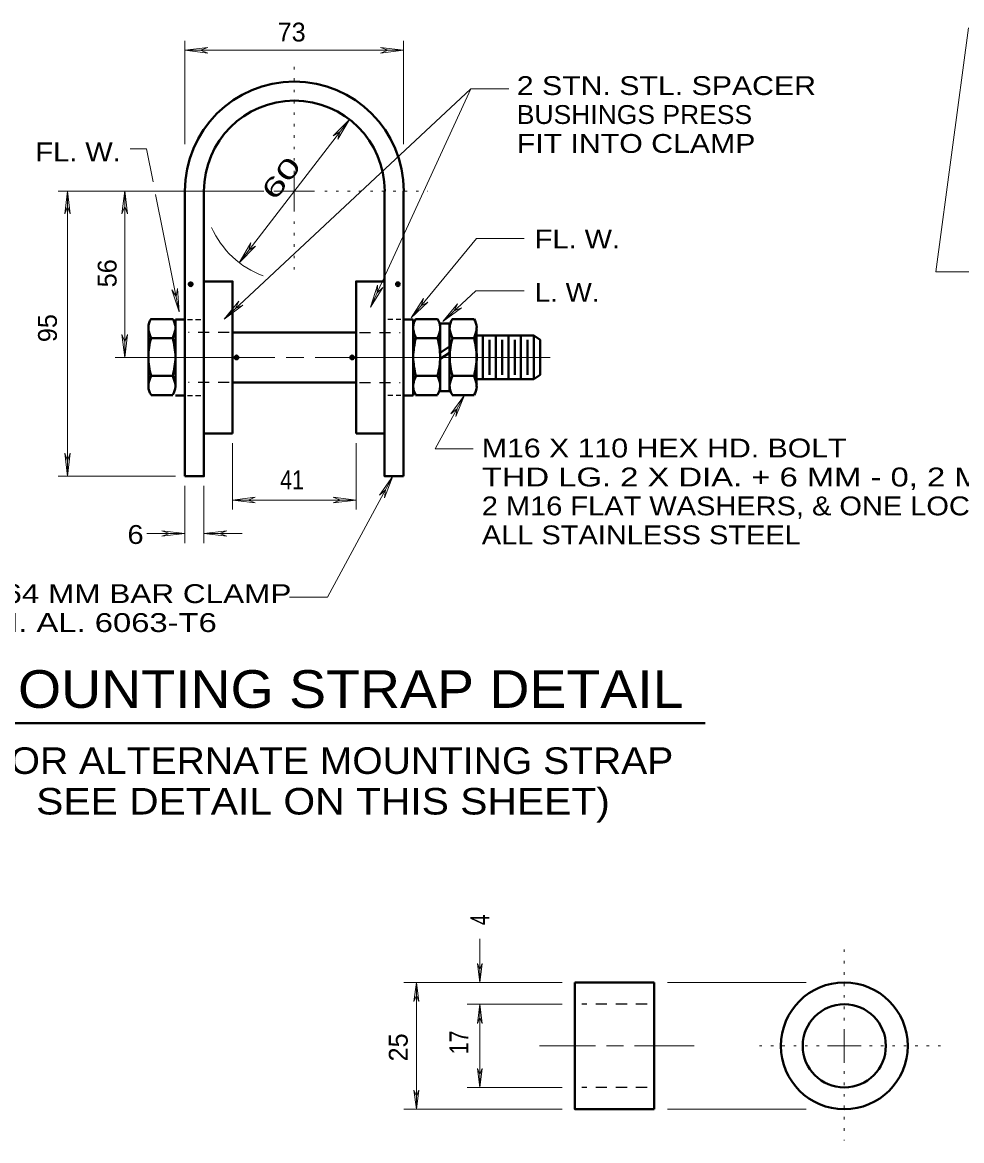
# Model space of a CAD drawing. Extents: x 312583 to 312854, y 144419 to 144597.
# Drawn here: x 312688.47 to 312726.34, y 144489.99 to 144535.08 of the extents above; entities that cross this region are included whole.
import ezdxf
from ezdxf.enums import TextEntityAlignment as Align

# ---------------------------------------------------------------- set-up
doc = ezdxf.new("R2010")
doc.units = 0
doc.header["$LTSCALE"] = 0.3
doc.header["$PDMODE"] = 32
doc.header["$PDSIZE"] = 0.15
doc.linetypes.add('DOTTED', pattern=[1.5, 0.3, -1.2])
doc.linetypes.add('SHORT_DASHED', pattern=[2.7, 1.5, -1.2])
doc.layers.add('1', color=7, linetype='Continuous', lineweight=40)

msp = doc.modelspace()

# ---------------------------------------------------------------- linework, layer by layer
at = {"layer": '1', "lineweight": 13}
for p, q in [((312695.0286, 144530.1636), (312695.0286, 144534.3343)), ((312703.8453, 144530.1636), (312703.8453, 144534.3343)), ((312695.0286, 144533.951), (312695.9486, 144534.066)), ((312695.0286, 144533.951), (312703.8453, 144533.951)), ((312695.0286, 144533.951), (312695.9486, 144533.836)), ((312695.9486, 144534.066), (312695.6573, 144533.951)), ((312695.9486, 144533.836), (312695.6573, 144533.951)), ((312702.9176, 144534.066), (312703.2166, 144533.951)), ((312703.8453, 144533.951), (312702.9176, 144534.066)), ((312702.9176, 144533.836), (312703.2166, 144533.951)), ((312703.8453, 144533.951), (312702.9176, 144533.836)), ((312696.608, 144523.118), (312706.5516, 144532.4023)), ((312702.5113, 144523.5933), (312706.5516, 144532.4023)), ((312706.5516, 144532.4023), (312708.085, 144532.4023)), ((312697.2136, 144525.3873), (312701.6603, 144531.168)), ((312701.6603, 144531.168), (312701.001, 144530.5086)), ((312701.6603, 144531.168), (312701.185, 144530.363)), ((312701.001, 144530.5086), (312701.277, 144530.6696)), ((312701.185, 144530.363), (312701.277, 144530.6696)), ((312692.8192, 144529.9828), (312693.4713, 144529.9828)), ((312693.4713, 144529.9828), (312693.7406, 144528.6456)), ((312699.437, 144528.2776), (312699.437, 144529.098)), ((312698.2103, 144528.2776), (312689.915, 144528.2776)), ((312690.2983, 144528.2776), (312690.1833, 144527.3576)), ((312690.2983, 144528.2776), (312690.2983, 144516.7776)), ((312690.2983, 144528.2776), (312690.4056, 144527.3576)), ((312692.5983, 144528.2853), (312692.4833, 144527.3576)), ((312692.5983, 144521.5693), (312692.5983, 144528.2853)), ((312692.5983, 144528.2853), (312692.7056, 144527.3576)), ((312693.8403, 144528.132), (312694.791, 144523.4093)), ((312699.437, 144528.2776), (312698.6166, 144528.2776)), ((312699.437, 144528.2776), (312699.437, 144527.4573)), ((312699.437, 144528.2776), (312700.2573, 144528.2776)), ((312690.1833, 144527.3576), (312690.2983, 144527.649)), ((312690.4056, 144527.3576), (312690.2983, 144527.649)), ((312692.4833, 144527.3576), (312692.5983, 144527.6566)), ((312692.7056, 144527.3576), (312692.5983, 144527.6566)), ((312697.2136, 144525.3873), (312697.689, 144526.1923)), ((312697.689, 144526.1923), (312697.597, 144525.8933)), ((312706.7893, 144526.361), (312704.152, 144523.164)), ((312706.7893, 144526.361), (312708.706, 144526.361)), ((312697.2136, 144525.3873), (312697.873, 144526.0543)), ((312697.873, 144526.0543), (312697.597, 144525.8933)), ((312694.4996, 144524.2986), (312694.6683, 144524.0303)), ((312694.791, 144523.4093), (312694.4996, 144524.2986)), ((312694.722, 144524.3446), (312694.6683, 144524.0303)), ((312694.791, 144523.4093), (312694.722, 144524.3446)), ((312702.5113, 144523.5933), (312702.795, 144524.4826)), ((312702.5113, 144523.5933), (312703.002, 144524.383)), ((312702.795, 144524.4826), (312702.7796, 144524.1683)), ((312703.002, 144524.383), (312702.7796, 144524.1683)), ((312696.608, 144523.118), (312697.206, 144523.8386)), ((312697.206, 144523.8386), (312697.068, 144523.5473)), ((312704.152, 144523.164), (312704.6503, 144523.946)), ((312704.6503, 144523.946), (312704.5506, 144523.647)), ((312706.7586, 144524.2526), (312705.4246, 144523.0183)), ((312706.7586, 144524.2526), (312708.6983, 144524.2526)), ((312696.608, 144523.118), (312697.3593, 144523.67)), ((312697.3593, 144523.67), (312697.068, 144523.5473)), ((312704.152, 144523.164), (312704.8266, 144523.8003)), ((312704.8266, 144523.8003), (312704.5506, 144523.647)), ((312705.4246, 144523.0183), (312706.0226, 144523.7313)), ((312705.4246, 144523.0183), (312706.1836, 144523.5626)), ((312706.0226, 144523.7313), (312705.8846, 144523.4476)), ((312706.1836, 144523.5626), (312705.8846, 144523.4476)), ((312692.4833, 144522.497), (312692.5983, 144522.198)), ((312692.5983, 144521.5693), (312692.4833, 144522.497)), ((312692.7056, 144522.497), (312692.5983, 144522.198)), ((312692.5983, 144521.5693), (312692.7056, 144522.497)), ((312698.655, 144521.5693), (312692.215, 144521.5693)), ((312699.8203, 144521.5693), (312699.115, 144521.5693)), ((312700.2803, 144521.5693), (312709.7563, 144521.5693)), ((312706.2986, 144520.0513), (312705.118, 144517.8893)), ((312706.2986, 144520.0513), (312705.7543, 144519.2923)), ((312706.2986, 144520.0513), (312705.9536, 144519.185)), ((312705.7543, 144519.2923), (312705.9996, 144519.4993)), ((312705.9536, 144519.185), (312705.9996, 144519.4993)), ((312696.9453, 144515.436), (312696.9453, 144518.1193)), ((312701.9286, 144515.436), (312701.9286, 144518.1193)), ((312690.1833, 144517.7053), (312690.2983, 144517.4063)), ((312690.2983, 144516.7776), (312690.1833, 144517.7053)), ((312690.4056, 144517.7053), (312690.2983, 144517.4063)), ((312690.2983, 144516.7776), (312690.4056, 144517.7053)), ((312706.6513, 144517.8893), (312705.118, 144517.8893)), ((312694.6453, 144516.7776), (312689.915, 144516.7776)), ((312703.416, 144516.7776), (312702.8716, 144516.0186)), ((312703.416, 144516.7776), (312703.0786, 144515.9113)), ((312695.0286, 144516.3943), (312695.0286, 144514.0866)), ((312695.7953, 144516.3943), (312695.7953, 144514.0866)), ((312702.8716, 144516.0186), (312703.117, 144516.2256)), ((312703.0786, 144515.9113), (312703.117, 144516.2256)), ((312696.9453, 144515.8193), (312697.8653, 144515.9343)), ((312696.9453, 144515.8193), (312701.9286, 144515.8193)), ((312696.9453, 144515.8193), (312697.8653, 144515.712)), ((312697.8653, 144515.9343), (312697.574, 144515.8193)), ((312697.8653, 144515.712), (312697.574, 144515.8193)), ((312701.0086, 144515.9343), (312701.3, 144515.8193)), ((312701.9286, 144515.8193), (312701.0086, 144515.9343)), ((312701.0086, 144515.712), (312701.3, 144515.8193)), ((312701.9286, 144515.8193), (312701.0086, 144515.712)), ((312695.0286, 144514.47), (312693.4953, 144514.47)), ((312694.101, 144514.585), (312694.4, 144514.47)), ((312695.0286, 144514.47), (312694.101, 144514.585)), ((312694.101, 144514.3626), (312694.4, 144514.47)), ((312695.0286, 144514.47), (312694.101, 144514.3626)), ((312695.7953, 144514.47), (312696.7153, 144514.585)), ((312697.3286, 144514.47), (312695.7953, 144514.47)), ((312695.7953, 144514.47), (312696.7153, 144514.3626)), ((312696.7153, 144514.585), (312696.424, 144514.47)), ((312696.7153, 144514.3626), (312696.424, 144514.47)), ((312706.9153, 144496.3731), (312706.9153, 144498.1342)), ((312706.8233, 144497.1397), (312706.9153, 144496.8944)), ((312706.9153, 144496.3731), (312706.8233, 144497.1397)), ((312707.015, 144497.1397), (312706.9153, 144496.8944)), ((312706.9153, 144496.3731), (312707.015, 144497.1397)), ((312710.2427, 144496.3731), (312703.8487, 144496.3731)), ((312704.3623, 144496.3731), (312704.2627, 144495.5987)), ((312704.3623, 144491.2594), (312704.3623, 144496.3731)), ((312704.3623, 144496.3731), (312704.462, 144495.5987)), ((312714.49, 144496.3731), (312720.079, 144496.3731)), ((312704.2627, 144495.5987), (312704.3623, 144495.8441)), ((312704.462, 144495.5987), (312704.3623, 144495.8441)), ((312710.2427, 144495.4914), (312706.4093, 144495.4914)), ((312706.9153, 144495.4914), (312706.8233, 144494.7171)), ((312706.9153, 144492.1411), (312706.9153, 144495.4914)), ((312706.9153, 144495.4914), (312707.015, 144494.7171)), ((312706.8233, 144494.7171), (312706.9153, 144494.9624)), ((312707.015, 144494.7171), (312706.9153, 144494.9624)), ((312721.6123, 144493.8124), (312721.6123, 144494.4947)), ((312711.5843, 144493.8124), (312709.3227, 144493.8124)), ((312712.7113, 144493.8124), (312712.0213, 144493.8124)), ((312713.1483, 144493.8124), (312715.5557, 144493.8124)), ((312721.6123, 144493.8124), (312720.93, 144493.8124)), ((312721.6123, 144493.8124), (312722.2947, 144493.8124)), ((312721.6123, 144493.8124), (312721.6123, 144493.1377)), ((312706.8233, 144492.9077), (312706.9153, 144492.6624)), ((312706.9153, 144492.1411), (312706.8233, 144492.9077)), ((312707.015, 144492.9077), (312706.9153, 144492.6624)), ((312706.9153, 144492.1411), (312707.015, 144492.9077)), ((312704.2627, 144492.0337), (312704.3623, 144491.7884)), ((312704.3623, 144491.2594), (312704.2627, 144492.0337)), ((312704.462, 144492.0337), (312704.3623, 144491.7884)), ((312704.3623, 144491.2594), (312704.462, 144492.0337)), ((312710.2427, 144492.1411), (312706.4093, 144492.1411)), ((312710.2427, 144491.2594), (312703.8487, 144491.2594)), ((312714.49, 144491.2594), (312720.079, 144491.2594))]:
    msp.add_line(p, q, dxfattribs=at)
at = {"layer": '1', "linetype": 'DOTTED', "lineweight": 13}
for p, q in [((312699.437, 144529.5043), (312699.437, 144533.4143)), ((312700.6636, 144528.2776), (312704.8266, 144528.2776)), ((312699.437, 144527.051), (312699.437, 144524.9503)), ((312721.6123, 144494.8397), (312721.6123, 144497.7837)), ((312720.5927, 144493.8124), (312718.078, 144493.8124)), ((312722.632, 144493.8124), (312725.6143, 144493.8124)), ((312721.6123, 144492.7927), (312721.6123, 144489.9944))]:
    msp.add_line(p, q, dxfattribs=at)
at = {"layer": '1'}
for p, q in [((312695.0286, 144516.7776), (312695.0286, 144528.2776)), ((312703.8453, 144516.7776), (312703.8453, 144528.2776)), ((312694.5456, 144523.118), (312693.664, 144523.118)), ((312694.6453, 144523.1026), (312695.0286, 144523.1026)), ((312694.6453, 144523.1026), (312694.6453, 144521.5693)), ((312704.2286, 144523.1026), (312703.8453, 144523.1026)), ((312704.2286, 144523.1026), (312704.2286, 144520.036)), ((312704.3283, 144523.118), (312705.21, 144523.118)), ((312705.3173, 144522.934), (312705.7006, 144522.934)), ((312705.3173, 144522.934), (312705.3173, 144522.7806)), ((312705.7006, 144522.934), (312705.7006, 144522.7806)), ((312705.8003, 144523.118), (312706.682, 144523.118)), ((312693.5566, 144522.7806), (312693.5566, 144521.5693)), ((312694.6453, 144522.7883), (312694.6453, 144521.5693)), ((312696.9453, 144522.5813), (312699.437, 144522.5813)), ((312701.9286, 144522.5813), (312699.437, 144522.5813)), ((312704.2286, 144522.7883), (312704.2286, 144521.5693)), ((312705.3173, 144522.7806), (312705.3173, 144521.5693)), ((312705.7006, 144522.7806), (312705.7006, 144521.5693)), ((312706.7893, 144522.7806), (312706.7893, 144521.5693)), ((312694.538, 144522.3513), (312693.664, 144522.3513)), ((312704.336, 144522.3513), (312705.21, 144522.3513)), ((312705.3173, 144521.761), (312705.7006, 144522.014)), ((312705.808, 144522.3513), (312706.682, 144522.3513)), ((312707.0423, 144522.4586), (312707.0423, 144521.5693)), ((312707.303, 144522.2746), (312707.303, 144521.5693)), ((312707.556, 144522.4586), (312707.556, 144521.5693)), ((312707.8166, 144522.2746), (312707.8166, 144521.5693)), ((312708.0696, 144522.4586), (312708.0696, 144521.5693)), ((312708.3226, 144522.2746), (312708.3226, 144521.5693)), ((312708.5756, 144522.4586), (312708.5756, 144521.5693)), ((312708.8363, 144522.2746), (312708.8363, 144521.5693)), ((312709.35, 144522.2746), (312709.0893, 144522.4586)), ((312709.35, 144522.2746), (312709.35, 144521.5693)), ((312693.5566, 144520.3963), (312693.5566, 144521.577)), ((312694.6453, 144520.3886), (312694.6453, 144521.5693)), ((312704.2286, 144520.3886), (312704.2286, 144521.5693)), ((312705.3173, 144521.508), (312705.7006, 144521.761)), ((312705.3173, 144520.3963), (312705.3173, 144521.577)), ((312705.7006, 144520.3886), (312705.7006, 144521.5693)), ((312706.7893, 144520.3886), (312706.7893, 144521.577)), ((312707.0423, 144520.6876), (312707.0423, 144521.577)), ((312707.303, 144520.8716), (312707.303, 144521.577)), ((312707.556, 144520.6876), (312707.556, 144521.577)), ((312707.8166, 144520.8716), (312707.8166, 144521.577)), ((312708.0696, 144520.6876), (312708.0696, 144521.577)), ((312708.3226, 144520.8716), (312708.3226, 144521.577)), ((312708.5756, 144520.6876), (312708.5756, 144521.577)), ((312708.8363, 144520.8716), (312708.8363, 144521.577)), ((312709.0893, 144520.6876), (312709.0893, 144521.577)), ((312709.35, 144520.8716), (312709.35, 144521.577)), ((312694.5456, 144520.8333), (312693.664, 144520.8333)), ((312704.3283, 144520.8333), (312705.21, 144520.8333)), ((312705.8003, 144520.8256), (312706.682, 144520.8256)), ((312706.7893, 144520.6876), (312709.0893, 144520.6876)), ((312709.35, 144520.8716), (312709.0893, 144520.6876)), ((312696.9453, 144520.565), (312699.437, 144520.565)), ((312701.9286, 144520.565), (312699.437, 144520.565)), ((312705.3173, 144520.2046), (312705.3173, 144520.3963)), ((312705.7006, 144520.3886), (312705.7006, 144520.2046)), ((312694.5456, 144520.0513), (312693.664, 144520.0513)), ((312694.6453, 144520.036), (312695.0286, 144520.036)), ((312704.2286, 144520.036), (312703.8453, 144520.036)), ((312704.3283, 144520.0513), (312705.21, 144520.0513)), ((312705.3173, 144520.2046), (312705.7006, 144520.2046)), ((312705.8003, 144520.0513), (312706.682, 144520.0513)), ((312696.9453, 144518.5026), (312695.7953, 144518.5026)), ((312701.9286, 144518.5026), (312703.0786, 144518.5026)), ((312685.6759, 144506.8265), (312716.0085, 144506.8265)), ((312713.9457, 144496.3731), (312710.7487, 144496.3731)), ((312713.9457, 144496.3731), (312713.9457, 144491.2594))]:
    msp.add_line(p, q, dxfattribs=at)
at = {"layer": '1', "lineweight": 25}
for p, q in [((312695.136, 144523.1026), (312695.3353, 144523.1026)), ((312695.458, 144523.1026), (312695.665, 144523.1026)), ((312703.416, 144523.1026), (312703.209, 144523.1026)), ((312703.738, 144523.1026), (312703.5386, 144523.1026)), ((312695.136, 144520.036), (312695.3353, 144520.036)), ((312695.458, 144520.036), (312695.665, 144520.036)), ((312703.416, 144520.036), (312703.209, 144520.036)), ((312703.738, 144520.036), (312703.5386, 144520.036))]:
    msp.add_line(p, q, dxfattribs=at)
at = {"layer": '1', "linetype": 'SHORT_DASHED', "lineweight": 25}
for p, q in [((312696.815, 144522.5813), (312695.1666, 144522.5813)), ((312702.059, 144522.5813), (312703.7073, 144522.5813)), ((312696.815, 144520.565), (312695.1666, 144520.565)), ((312702.059, 144520.565), (312703.7073, 144520.565)), ((312713.662, 144495.4914), (312711.0323, 144495.4914)), ((312713.662, 144492.1411), (312711.0323, 144492.1411))]:
    msp.add_line(p, q, dxfattribs=at)
at = {"layer": '1', "lineweight": 13}
for points in [[(312726.6142, 144534.8615), (312725.3075, 144525.0233), (312728.1825, 144525.0233)], [(312703.416, 144516.7776), (312700.771, 144511.9016), (312699.2376, 144511.9016)]]:
    msp.add_lwpolyline(points, dxfattribs=at)
at = {"layer": '1'}
for points in [[(312695.0286, 144516.7776), (312695.7953, 144516.7776), (312695.7953, 144528.2776)], [(312703.8453, 144516.7776), (312703.0786, 144516.7776), (312703.0786, 144528.2776)], [(312695.7953, 144524.636), (312696.9453, 144524.636), (312696.9453, 144518.5026)], [(312703.0786, 144524.636), (312701.9286, 144524.636), (312701.9286, 144518.5026)], [(312706.7893, 144522.4586), (312709.0893, 144522.4586), (312709.0893, 144521.5693)], [(312713.9457, 144491.2594), (312710.7487, 144491.2594), (312710.7487, 144496.3731)]]:
    msp.add_lwpolyline(points, dxfattribs=at)
for radius in [2.5556, 1.6764]:
    msp.add_circle((312721.6123, 144493.815), radius, dxfattribs=at)
for centre, radius, start, end in [((312699.437, 144528.2792), 4.4099, 90, 180), ((312699.437, 144528.2792), 4.4099, 0, 90), ((312699.437, 144528.2792), 3.6432, 90, 180), ((312699.437, 144528.2792), 3.6432, 0, 90), ((312694.1853, 144522.7663), 0.6314, 145.8703, 178.33743), ((312694.0114, 144522.7663), 0.6314, 1.66257, 34.1297), ((312704.8626, 144522.7663), 0.6314, 145.8703, 178.33743), ((312704.6886, 144522.7663), 0.6314, 1.66257, 34.1297), ((312706.3346, 144522.7632), 0.6314, 145.8703, 178.33743), ((312706.1606, 144522.7632), 0.6314, 1.66257, 34.1297), ((312695.3225, 144523.0712), 1.8081, 191.77014, 203.36365), ((312692.8742, 144523.0712), 1.8081, 336.63635, 348.22986), ((312705.9997, 144523.0712), 1.8081, 191.77014, 203.36365), ((312703.5515, 144523.0712), 1.8081, 336.63635, 348.22986), ((312707.4717, 144523.0681), 1.8081, 191.77014, 203.36365), ((312705.0235, 144523.0681), 1.8081, 336.63635, 348.22986), ((312696.8145, 144521.5095), 3.263, 164.99798, 178.595), ((312691.3822, 144521.5095), 3.263, 1.405, 15.00202), ((312707.4917, 144521.5095), 3.263, 164.99798, 178.595), ((312702.0595, 144521.5095), 3.263, 1.405, 15.00202), ((312708.9637, 144521.5065), 3.263, 164.99798, 178.595), ((312703.5315, 144521.5065), 3.263, 1.405, 15.00202), ((312696.8145, 144521.6696), 3.263, 181.405, 195.00202), ((312691.3822, 144521.6696), 3.263, 344.99798, 358.595), ((312707.4917, 144521.6696), 3.263, 181.405, 195.00202), ((312702.0595, 144521.6696), 3.263, 344.99798, 358.595), ((312708.9637, 144521.6665), 3.263, 181.405, 195.00202), ((312703.5315, 144521.6665), 3.263, 344.99798, 358.595), ((312695.3225, 144520.1079), 1.8081, 156.63635, 168.22986), ((312692.8742, 144520.1079), 1.8081, 11.77014, 23.36365), ((312705.9997, 144520.1079), 1.8081, 156.63635, 168.22986), ((312703.5515, 144520.1079), 1.8081, 11.77014, 23.36365), ((312707.4717, 144520.1048), 1.8081, 156.63635, 168.22986), ((312705.0235, 144520.1048), 1.8081, 11.77014, 23.36365), ((312694.1853, 144520.4128), 0.6314, 181.66257, 214.1297), ((312694.0114, 144520.4128), 0.6314, 325.8703, 358.33743), ((312704.8626, 144520.4128), 0.6314, 181.66257, 214.1297), ((312704.6886, 144520.4128), 0.6314, 325.8703, 358.33743), ((312706.3346, 144520.4097), 0.6314, 181.66257, 214.1297), ((312706.1606, 144520.4097), 0.6314, 325.8703, 358.33743)]:
    msp.add_arc(centre, radius, start, end, dxfattribs=at)
at = {"layer": '1', "lineweight": 13}
msp.add_arc((312699.437, 144528.2792), 3.6432, 203.82541, 249.8142, dxfattribs=at)
at = {"layer": '1'}
for p in [(312695.2586, 144524.521), (312703.6153, 144524.521), (312697.1063, 144521.5693), (312701.7676, 144521.5693)]:
    msp.add_point(p, dxfattribs=at)

# ---------------------------------------------------------------- texts
msp.add_text('73', height=0.76, dxfattribs=at).set_placement((312698.7644, 144534.3066))
for s, width, p in [('2 STN. STL. SPACER', 1.2, (312708.407, 144532.1483)), ('BUSHINGS PRESS', 1.05, (312708.407, 144530.982)), ('FIT INTO CLAMP', 1.2, (312708.407, 144529.8157)), ('FL. W.', 1.15, (312688.9977, 144529.4757)), ('FL. W.', 1.15, (312709.1303, 144525.9656)), ('L. W.', 1.1, (312709.1341, 144523.8131)), ('M16 X 110 HEX HD. BOLT', 1.2, (312706.9963, 144517.5356)), ('THD LG. 2 X DIA. + 6 MM - 0, 2 M16 HEX NUTS,', 1.3, (312706.9963, 144516.3693)), ('41', 0.85, (312698.8641, 144516.2534)), ('2 M16 FLAT WASHERS, & ONE LOCK WASHER', 1.15, (312706.9963, 144515.203)), ('6 ', 1.15, (312692.7092, 144514.0506)), ('ALL STAINLESS STEEL', 1.15, (312706.9963, 144514.0367)), ('6 BY 64 MM BAR CLAMP', 1.25, (312684.6356, 144511.6659)), ('ALUM. AL. 6063-T6', 1.3, (312684.6356, 144510.4996))]:
    msp.add_text(s, height=0.76, dxfattribs=dict(at, width=width)).set_placement(p)
for s, rotation, width, p in [('60', 52.455, 1.6, (312698.6568, 144527.8519)), ('4', 90, 0.75, (312707.2963, 144498.6843)), ('17', 90, 0.85, (312706.4539, 144493.4735))]:
    msp.add_text(s, height=0.76, rotation=rotation, dxfattribs=dict(at, width=width)).set_placement(p)
for s, p in [('56', (312692.271, 144524.3953)), ('95', (312689.8648, 144522.1861)), ('25', (312704.0073, 144493.1881))]:
    msp.add_text(s, height=0.76, rotation=90, dxfattribs=at).set_placement(p)
for s, height, width, p in [('MOUNTING STRAP DETAIL', 1.52, 1.1, (312700.7824, 144507.4408)), ('(FOR ALTERNATE MOUNTING STRAP', 1.07, 1.1, (312700.5946, 144504.7794)), ('SEE DETAIL ON THIS SHEET)', 1.07, 1.15, (312700.5946, 144503.1421))]:
    msp.add_text(s, height=height, dxfattribs=dict(at, width=width)).set_placement(p, align=Align.CENTER)

doc.saveas('drawing.dxf')
